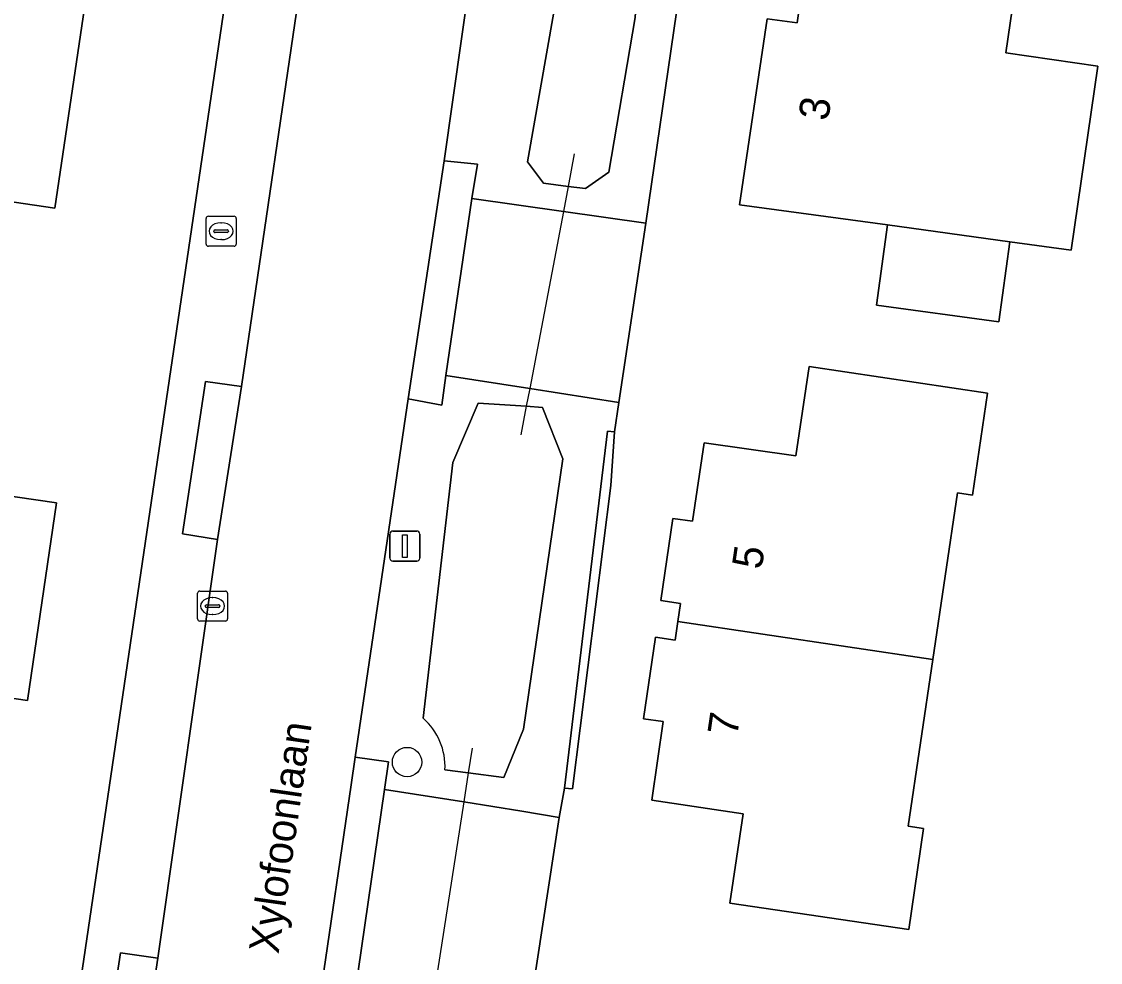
# Model space of a CAD drawing. Extents: x 164148 to 165261, y 382513 to 383432.
# Drawn here: x 164659.65 to 164695.47, y 383076.71 to 383107.95 of the extents above; entities that cross this region are included whole.
import ezdxf

# ---------------------------------------------------------------- set-up
doc = ezdxf.new("R2010")
doc.units = 0
for name, color, linetype in [('IMGEO_Boom', 7, 'Continuous'), ('IMGEO_Brandkraan', 7, 'Continuous'), ('IMGEO_Duiker', 7, 'Continuous'), ('IMGEO_Erf', 7, 'Continuous'), ('IMGEO_Greppel_droge_sloot', 7, 'Continuous'), ('IMGEO_Groenvoorziening', 7, 'Continuous'), ('IMGEO_Haag', 7, 'Continuous'), ('IMGEO_Kolk', 7, 'Continuous'), ('IMGEO_Lichtmast', 7, 'Continuous'), ('IMGEO_Openbare_ruimte_label', 7, 'Continuous'), ('IMGEO_Pand', 7, 'Continuous'), ('IMGEO_Pand_nummerreeks', 7, 'Continuous'), ('IMGEO_Rijbaan_lokaal_open', 7, 'Continuous'), ('IMGEO_Voetpad_open', 7, 'Continuous')]:
    doc.layers.add(name, color=color, linetype=linetype)

msp = doc.modelspace()

# ---------------------------------------------------------------- linework, layer by layer
at = {"layer": 'IMGEO_Boom'}
msp.add_circle((164672.45, 383083.364), 0.489, dxfattribs=at)
at = {"layer": 'IMGEO_Brandkraan'}
for p, q in [((164665.852, 383101.491), (164666.704, 383101.491)), ((164665.777, 383100.565), (164665.777, 383101.417)), ((164666.265, 383101.271), (164666.29, 383101.271)), ((164666.778, 383101.417), (164666.778, 383100.565)), ((164666.036, 383100.985), (164666.036, 383100.997)), ((164666.474, 383100.948), (164666.076, 383100.948)), ((164666.079, 383101.034), (164666.477, 383101.034)), ((164666.52, 383100.997), (164666.52, 383100.985)), ((164666.704, 383100.491), (164665.852, 383100.491)), ((164666.288, 383100.711), (164666.263, 383100.711))]:
    msp.add_line(p, q, dxfattribs=at)
for points in [[(164665.852, 383101.491), (164666.704, 383101.491)], [(164665.777, 383100.565), (164665.777, 383101.417)], [(164666.778, 383101.417), (164666.778, 383100.565)], [(164666.704, 383100.491), (164665.852, 383100.491)]]:
    msp.add_lwpolyline(points, dxfattribs=at)
for centre, radius, start, end in [((164665.854, 383101.415), 0.0765, 91.552, 178.448), ((164665.854, 383101.415), 0.0765, 91.552, 178.448), ((164666.702, 383101.415), 0.0765, 1.552, 88.448), ((164666.702, 383101.415), 0.0765, 1.552, 88.448), ((164666.076, 383100.994), 0.0403, 85.8775, 175.7526), ((164666.073, 383100.984), 0.0366, 178.938, 274.7102), ((164666.477, 383100.991), 0.043, 264.8664, 352.4533), ((164666.481, 383100.996), 0.0386, 1.7309, 96.639), ((164665.854, 383100.567), 0.0765, 181.552, 268.448), ((164665.854, 383100.567), 0.0765, 181.552, 268.448), ((164666.702, 383100.567), 0.0765, 271.552, 358.448), ((164666.702, 383100.567), 0.0765, 271.552, 358.448)]:
    msp.add_arc(centre, radius, start, end, dxfattribs=at)
for centre, major_axis, ratio, start_param, end_param in [((164666.264, 383100.991), (-0.387, 0.002), 0.722429, 4.712389, 7.853982), ((164666.289, 383100.991), (-0.39, 0.002), 0.717154, 1.570796, 4.712389)]:
    msp.add_ellipse(centre, major_axis=major_axis, ratio=ratio, start_param=start_param, end_param=end_param, dxfattribs=at)
at = {"layer": 'IMGEO_Duiker'}
for points in [[(164678.002, 383103.555), (164677.798, 383102.481), (164677.639, 383101.645), (164676.521, 383095.769), (164676.409, 383095.178), (164676.228, 383094.227)], [(164674.609, 383083.821), (164674.482, 383083.009), (164674.332, 383082.043), (164673.405, 383076.084), (164673.174, 383074.602), (164673.075, 383073.962), (164673.013, 383073.569)]]:
    msp.add_lwpolyline(points, dxfattribs=at)
at = {"layer": 'IMGEO_Erf'}
for points in [[(164623.816, 383163.728), (164623.27, 383160.3), (164619.179, 383132.443), (164618.352, 383126.809), (164615.891, 383110.249), (164614.945, 383103.98), (164613.433, 383093.793), (164612.816, 383089.325), (164610.85, 383076.068), (164610.275, 383072.012), (164608.947, 383063.175), (164608.549, 383060.35), (164603.815, 383028.066), (164603.697, 383027.909), (164653.403, 383020.558), (164672.613, 383150.649)], [(164685.42, 383135.126), (164682.705, 383117.517), (164682.279, 383114.453), (164685.334, 383113.998), (164688.257, 383113.615), (164687.868, 383110.687), (164684.941, 383111.045), (164681.864, 383111.47), (164680.372, 383101.254), (164679.477, 383095.307), (164679.334, 383094.335), (164679.22, 383092.548), (164677.944, 383082.474), (164677.674, 383082.494), (164677.503, 383081.521), (164676.599, 383075.668), (164674.064, 383058.631), (164743.462, 383048.39), (164750.216, 383047.411), (164757.629, 383053.516), (164711.831, 383108.452)]]:
    msp.add_lwpolyline(points, dxfattribs=at)
for points in [[(164654.961, 383116.507), (164661.44, 383115.544), (164660.987, 383112.586), (164662.326, 383112.378), (164660.751, 383101.757), (164652.943, 383102.91)], [(164694.494, 383100.363), (164692.457, 383100.642), (164692.092, 383097.977), (164688.03, 383098.534), (164688.395, 383101.199), (164683.491, 383101.872), (164684.404, 383108.045), (164685.4, 383107.912), (164685.832, 383110.885), (164689.611, 383110.336), (164692.759, 383109.878), (164692.328, 383106.91), (164695.381, 383106.466)], [(164648.326, 383097.049), (164650.388, 383096.745), (164652.441, 383096.441), (164659.204, 383095.441), (164658.742, 383092.267), (164660.811, 383091.968), (164659.847, 383085.409), (164648.946, 383087.019), (164649.545, 383091.057), (164647.486, 383091.362)], [(164691.218, 383092.228), (164690.728, 383092.301), (164689.907, 383086.771), (164689.085, 383081.24), (164689.599, 383081.164), (164689.105, 383077.805), (164683.169, 383078.677), (164683.611, 383081.643), (164680.574, 383082.104), (164680.956, 383084.708), (164680.303, 383084.804), (164680.7, 383087.51), (164681.353, 383087.414), (164681.443, 383088.028), (164681.531, 383088.632), (164680.878, 383088.728), (164681.278, 383091.454), (164681.931, 383091.358), (164682.314, 383093.967), (164685.361, 383093.531), (164685.804, 383096.496), (164691.724, 383095.61)]]:
    msp.add_lwpolyline(points, close=True, dxfattribs=at)
at = {"layer": 'IMGEO_Greppel_droge_sloot'}
msp.add_lwpolyline([(164680.019, 383108.086), (164680.118, 383109.601), (164680.046, 383110.526), (164679.619, 383111.203), (164679.151, 383111.27), (164678.622, 383111.346), (164677.731, 383110.883), (164677.531, 383109.471), (164676.449, 383103.297), (164676.984, 383102.585), (164677.798, 383102.481), (164678.372, 383102.407), (164679.153, 383102.95)], close=True, dxfattribs=at)
for points in [[(164677.626, 383093.43), (164676.948, 383095.142), (164676.409, 383095.178), (164674.811, 383095.284), (164673.965, 383093.315), (164672.986, 383084.821)], [(164673.707, 383083.11), (164674.482, 383083.009), (164675.666, 383082.856), (164676.313, 383084.457), (164677.626, 383093.43)]]:
    msp.add_lwpolyline(points, dxfattribs=at)
msp.add_arc((164671.561, 383083.213), 2.149, 357.2539, 48.4463, dxfattribs=at)
at = {"layer": 'IMGEO_Groenvoorziening'}
for points in [[(164681.864, 383111.47), (164681.89, 383111.65), (164679.265, 383112.022), (164676.149, 383112.464), (164676.023, 383111.451), (164674.86, 383111.597), (164673.679, 383103.33), (164674.787, 383103.219), (164674.604, 383102.079), (164677.639, 383101.645), (164680.372, 383101.254)], [(164677.531, 383109.471), (164677.731, 383110.883), (164678.622, 383111.346), (164679.151, 383111.27), (164679.619, 383111.203), (164680.046, 383110.526), (164680.118, 383109.601), (164680.019, 383108.086), (164679.153, 383102.95), (164678.372, 383102.407), (164677.798, 383102.481), (164676.984, 383102.585), (164676.449, 383103.297)], [(164679.334, 383094.335), (164679.477, 383095.307), (164676.521, 383095.769), (164673.742, 383096.204), (164673.609, 383095.219), (164672.483, 383095.429), (164670.732, 383083.53), (164671.833, 383083.368), (164671.702, 383082.459), (164674.332, 383082.043), (164676.256, 383081.738), (164677.503, 383081.521), (164677.674, 383082.494), (164679.102, 383094.347)], [(164679.22, 383092.548), (164679.334, 383094.335), (164679.102, 383094.347), (164677.674, 383082.494), (164677.944, 383082.474)]]:
    msp.add_lwpolyline(points, close=True, dxfattribs=at)
msp.add_lwpolyline([(164672.986, 383084.821), (164673.965, 383093.315), (164674.811, 383095.284), (164676.409, 383095.178), (164676.948, 383095.142), (164677.626, 383093.43), (164676.313, 383084.457), (164675.666, 383082.856), (164674.482, 383083.009), (164673.707, 383083.11)], dxfattribs=at)
msp.add_arc((164671.561, 383083.213), 2.149, 357.2539, 48.4463, dxfattribs=at)
at = {"layer": 'IMGEO_Haag'}
msp.add_lwpolyline([(164679.22, 383092.548), (164679.334, 383094.335), (164679.102, 383094.347), (164677.674, 383082.494), (164677.944, 383082.474)], close=True, dxfattribs=at)
at = {"layer": 'IMGEO_Kolk'}
for p, q in [((164665.491, 383088.118), (164665.491, 383088.97)), ((164665.566, 383089.044), (164666.418, 383089.044)), ((164666.492, 383088.97), (164666.492, 383088.118)), ((164665.793, 383088.587), (164666.191, 383088.587)), ((164665.979, 383088.824), (164666.004, 383088.824)), ((164665.75, 383088.538), (164665.75, 383088.55)), ((164666.188, 383088.501), (164665.79, 383088.501)), ((164666.002, 383088.264), (164665.977, 383088.264)), ((164666.234, 383088.55), (164666.234, 383088.538)), ((164666.418, 383088.044), (164665.566, 383088.044))]:
    msp.add_line(p, q, dxfattribs=at)
for points in [[(164665.491, 383088.118), (164665.491, 383088.97)], [(164665.566, 383089.044), (164666.418, 383089.044)], [(164666.492, 383088.97), (164666.492, 383088.118)], [(164666.418, 383088.044), (164665.566, 383088.044)]]:
    msp.add_lwpolyline(points, dxfattribs=at)
for centre, radius, start, end in [((164665.568, 383088.968), 0.0765, 91.552, 178.448), ((164665.568, 383088.968), 0.0765, 91.552, 178.448), ((164666.416, 383088.968), 0.0765, 1.552, 88.448), ((164666.416, 383088.968), 0.0765, 1.552, 88.448), ((164665.79, 383088.547), 0.0403, 85.8775, 175.7526), ((164666.195, 383088.549), 0.0386, 1.7309, 96.639), ((164665.787, 383088.537), 0.0366, 178.938, 274.7102), ((164666.191, 383088.544), 0.043, 264.8664, 352.4533), ((164665.568, 383088.12), 0.0765, 181.552, 268.448), ((164665.568, 383088.12), 0.0765, 181.552, 268.448), ((164666.416, 383088.12), 0.0765, 271.552, 358.448), ((164666.416, 383088.12), 0.0765, 271.552, 358.448)]:
    msp.add_arc(centre, radius, start, end, dxfattribs=at)
for centre, major_axis, ratio, start_param, end_param in [((164665.978, 383088.544), (-0.387, 0.002), 0.722429, 4.712389, 7.853982), ((164666.003, 383088.544), (-0.39, 0.002), 0.717154, 1.570796, 4.712389)]:
    msp.add_ellipse(centre, major_axis=major_axis, ratio=ratio, start_param=start_param, end_param=end_param, dxfattribs=at)
at = {"layer": 'IMGEO_Lichtmast'}
for p, q in [((164671.879, 383090.134), (164671.879, 383090.934)), ((164671.879, 383090.934), (164671.879, 383090.134)), ((164671.979, 383091.034), (164672.769, 383091.034)), ((164672.769, 383091.034), (164671.979, 383091.034)), ((164672.869, 383090.934), (164672.869, 383090.134)), ((164672.869, 383090.134), (164672.869, 383090.934)), ((164672.769, 383090.034), (164671.979, 383090.034)), ((164671.979, 383090.034), (164672.769, 383090.034))]:
    msp.add_line(p, q, dxfattribs=at)
msp.add_lwpolyline([(164672.299, 383090.909), (164672.449, 383090.909), (164672.449, 383090.159), (164672.299, 383090.159), (164672.299, 383090.909)], dxfattribs=at)
for centre, start, end in [((164671.979, 383090.934), 90, 180), ((164671.979, 383090.934), 90, 180), ((164672.769, 383090.934), 0, 90), ((164672.769, 383090.934), 360, 90), ((164671.979, 383090.134), 180, 270), ((164671.979, 383090.134), 180, 270), ((164672.769, 383090.134), 270, 0), ((164672.769, 383090.134), 270, 0)]:
    msp.add_arc(centre, 0.1, start, end, dxfattribs=at)
at = {"layer": 'IMGEO_Pand'}
for points in [[(164660.751, 383101.757), (164662.326, 383112.378), (164660.987, 383112.586), (164661.44, 383115.544), (164654.961, 383116.507), (164652.943, 383102.91)], [(164692.328, 383106.91), (164692.759, 383109.878), (164689.611, 383110.336), (164685.832, 383110.885), (164685.4, 383107.912), (164684.404, 383108.045), (164683.491, 383101.872), (164688.395, 383101.199), (164692.457, 383100.642), (164694.494, 383100.363), (164695.381, 383106.466)], [(164692.457, 383100.642), (164688.395, 383101.199), (164688.03, 383098.534), (164692.092, 383097.977)], [(164660.811, 383091.968), (164658.742, 383092.267), (164659.204, 383095.441), (164652.441, 383096.441), (164650.388, 383096.745), (164648.326, 383097.049), (164647.486, 383091.362), (164649.545, 383091.057), (164648.946, 383087.019), (164659.847, 383085.409)], [(164690.728, 383092.301), (164691.218, 383092.228), (164691.724, 383095.61), (164685.804, 383096.496), (164685.361, 383093.531), (164682.314, 383093.967), (164681.931, 383091.358), (164681.278, 383091.454), (164680.878, 383088.728), (164681.531, 383088.632), (164681.443, 383088.028), (164689.907, 383086.771)], [(164689.907, 383086.771), (164681.443, 383088.028), (164681.353, 383087.414), (164680.7, 383087.51), (164680.303, 383084.804), (164680.956, 383084.708), (164680.574, 383082.104), (164683.611, 383081.643), (164683.169, 383078.677), (164689.105, 383077.805), (164689.599, 383081.164), (164689.085, 383081.24)]]:
    msp.add_lwpolyline(points, close=True, dxfattribs=at)
at = {"layer": 'IMGEO_Rijbaan_lokaal_open'}
msp.add_lwpolyline([(164673.679, 383103.33), (164674.86, 383111.597), (164676.045, 383119.511), (164677.103, 383126.885), (164671.68, 383127.772), (164669.899, 383115.549), (164669.137, 383110.698), (164666.957, 383095.84), (164666.161, 383090.76), (164664.173, 383076.85), (164663.423, 383071.905), (164663.405, 383071.768), (164663.299, 383071.06), (164668.78, 383070.285), (164669.564, 383075.59), (164670.596, 383082.607), (164670.732, 383083.53), (164672.483, 383095.429)], close=True, dxfattribs=at)
at = {"layer": 'IMGEO_Voetpad_open'}
for points in [[(164666.161, 383090.76), (164664.995, 383090.947), (164665.754, 383095.997), (164666.957, 383095.84), (164669.137, 383110.698), (164667.959, 383110.888), (164668.674, 383115.736), (164669.899, 383115.549), (164671.68, 383127.772), (164671.889, 383129.204), (164670.698, 383129.426), (164671.449, 383134.735), (164672.668, 383134.547), (164675.108, 383151.287), (164675.111, 383151.432)], [(164672.613, 383150.649), (164653.403, 383020.558), (164653.018, 383017.951), (164651.876, 383010.215), (164651.419, 383007.225), (164650.705, 383001.947), (164653.078, 383001.462), (164657.714, 383033.452), (164656.509, 383033.621), (164657.237, 383038.501), (164658.441, 383038.338), (164659.675, 383046.714), (164660.382, 383051.508), (164663.299, 383071.06), (164663.405, 383071.768), (164663.423, 383071.905), (164662.198, 383072.123), (164662.932, 383077.035), (164664.173, 383076.85), (164666.161, 383090.76)]]:
    msp.add_lwpolyline(points, dxfattribs=at)
for points in [[(164674.604, 383102.079), (164674.787, 383103.219), (164673.679, 383103.33), (164672.483, 383095.429), (164673.609, 383095.219), (164673.742, 383096.204)], [(164680.372, 383101.254), (164677.639, 383101.645), (164674.604, 383102.079), (164673.742, 383096.204), (164676.521, 383095.769), (164679.477, 383095.307)], [(164666.161, 383090.76), (164666.957, 383095.84), (164665.754, 383095.997), (164664.995, 383090.947)], [(164671.702, 383082.459), (164671.833, 383083.368), (164670.732, 383083.53), (164670.596, 383082.607), (164669.564, 383075.59), (164670.675, 383075.453), (164670.831, 383076.42)], [(164677.503, 383081.521), (164676.256, 383081.738), (164674.332, 383082.043), (164671.702, 383082.459), (164670.831, 383076.42), (164673.405, 383076.084), (164676.194, 383075.721), (164676.599, 383075.668)], [(164663.423, 383071.905), (164664.173, 383076.85), (164662.932, 383077.035), (164662.198, 383072.123)]]:
    msp.add_lwpolyline(points, close=True, dxfattribs=at)

# ---------------------------------------------------------------- texts
at = {"layer": 'IMGEO_Openbare_ruimte_label'}
msp.add_text('Xylofoonlaan', height=1, rotation=81.7808, dxfattribs=at).set_placement((164668.182, 383076.974))
msp.add_text('Xylofoonlaan', height=1, rotation=81.7808, dxfattribs=at).set_placement((164668.182, 383076.974))
at = {"layer": 'IMGEO_Pand_nummerreeks'}
for s, rotation, p in [('3', 81.5892, (164686.427, 383104.632)), ('5', 81.6465, (164684.219, 383089.736)), ('7', 81.6522, (164683.407, 383084.195))]:
    msp.add_text(s, height=1, rotation=rotation, dxfattribs=at).set_placement(p)

doc.saveas('drawing.dxf')
